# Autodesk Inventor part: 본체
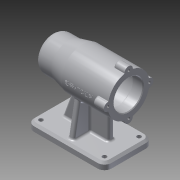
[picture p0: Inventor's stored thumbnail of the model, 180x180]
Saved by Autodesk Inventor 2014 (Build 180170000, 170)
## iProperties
Created: 2019-07
Part Number: 본체
Material: Aluminum 6061
Document SubType Name: Modeling
Designer: kh
Density: 2.71 g/cm^3
Appearance: Aluminum - Flat
Mass: 649.774 g
Surface Area: 647.594 cm^2
Volume: 239.769 cm^3
Author: kh
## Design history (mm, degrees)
sketch "Sketch1"
  geometry: L1 (-56, -35)-(56, -35); L2 (56, -35)-(56, 35); L3 (56, 35)-(-56, 35); L4 (-56, 35)-(-56, -35); L5 (-56, -35)-(56, 35); L6 (56, -35)-(-56, 35); 1 further point
  constraints: 12 end point, 2 midpoint, 2 parallel, 1 horizontal, 1 perpendicular
  dimensions: "d0" = 112 distance of L2.end L3.end; "d1" = 70 distance of L1.end L2.end
extrude "Extrusion1" new body sketch "Sketch1" distance "d2" = 10; taper "d3" = 0 deg
workplane "Work Plane1"
sketch "Sketch2"
  geometry: L1 (0, 80)-(112, 80); L2 (112, 0)-(0, 0) reference; L3 (112, 80)-(112, 110); L4 (112, 110)-(45, 110); L5 (45, 110)-(25, 105); L6 (25, 105)-(0, 105); L7 (0, 105)-(0, 80); 1 further point
  constraints: 12 end point, 2 parallel, 2 perpendicular, 1 horizontal, 1 vertical alignment
  dimensions: "d4" = 80 distance between parallel lines of L1 L2; "d5" = 60 diameter of L4 L1; "d6" = 50 diameter of L6 L1; "d7" = 25 distance of L5.end L6.end; "d8" = 45 horizontal distance of L4.end L6.end; "d9" = 112 distance between parallel lines of L3 L7
revolve "Revolution1" sketch "Sketch2" stored, may be unused: angle "d10" = 90 deg
sketch "Sketch3"
  geometry: L1 (112, 10)-(0, 10) reference; L2 (20, 10)-(39.872, 64.598); L3 (39.872, 64.598)-(87, 64.598); L4 (87, 64.598)-(87, 10); 1 further point
  constraints: 6 end point, 2 point on line, 1 parallel, 1 perpendicular
  dimensions: "d11" = 25 distance of L4.end L1.start; "d12" = 20 distance of L2.start L1.end; "d13" = 110 deg angle of L2 L1; "d14" = 47.12798 distance of L2.end L3.end
extrude "Extrusion2" join sketch "Sketch3" stored distance "d15" = 8; taper "d16" = 0 deg
workplane "Work Plane2"
sketch "Sketch4"
  geometry: L1 (-10, 70)-(-10, 0) reference; L2 (-10, 7)-(-57.334, 15.346); L3 (-10, 63)-(-57.334, 54.654); A1 r 30 centre (-80, 35) between (-50.268, 39) and (-50.268, 31) reference; 1 further point
  constraints: 4 end point, 2 point on circle, 2 point on line
  dimensions: "d18" = 7 distance of L2.start L1.end; "d19" = 7 distance of L3.start L1.start; "d20" = 100 deg angle of L3 L1; "d21" = 100 deg angle of L2 L1
extrude "Extrusion3" join sketch "Sketch4" stored distance "d22" = 8; taper "d23" = 0 deg
sketch "Sketch6"
  geometry: C1 r 6 at (0, 30); C2 r 6 at (-30, 0); C3 r 6 at (0, -30); C4 r 6 at (30, 0); 2 further points
  constraints: 4 centre point, 2 vertical alignment, 10 other
  dimensions: "d41" = 6 radius of C1; "d44" = 360 deg dimension on point (0, 0) C1.centre (derived)
extrude "Extrusion4" join sketch "Sketch6" distance "d46" = 16; taper "d47" = 0 deg
sketch "Sketch5"
  geometry: L1 (56, 80)-(-56, 80); L2 (56, 0)-(-56, 0) reference; L3 (56, 105)-(56, 55) reference; L4 (-56, 110)-(-56, 50) reference; L5 (-56, 101)-(-41, 101); L6 (-41, 101)-(-41, 101); L7 (-38, 104)-(10, 104); L8 (13, 101)-(13, 101); L9 (13, 101)-(24.7, 101); L10 (25, 100.7)-(25, 97.5); L11 (25, 97.5)-(42.7, 97.5); L12 (43, 97.2)-(43, 96); L13 (43, 96)-(46.7, 96); L14 (47, 95.7)-(47, 90.5); L15 (47, 90.5)-(47, 90.5); L16 (50, 87.5)-(50, 80); A1 r 0.3 centre (24.7, 100.7) between (25, 100.7) and (24.7, 101); A2 r 0.3 centre (42.7, 97.2) between (43, 97.2) and (42.7, 97.5); A3 r 0.3 centre (46.7, 95.7) between (47, 95.7) and (46.7, 96); A4 r 3 centre (10, 101) between (13, 101) and (10, 104); A5 r 3 centre (-38, 101) between (-38, 104) and (-41, 101); A6 r 3 centre (47, 87.5) between (50, 87.5) and (47, 90.5); 7 further points
  constraints: 26 end point, 14 point on line, 12 point on circle, 12 tangent, 8 parallel, 6 centre point, 3 equal radius, 3 perpendicular, 2 midpoint, 1 collinear, 1 horizontal
  dimensions: "d24" = 80 distance between parallel lines of L1 L2; "d25" = 42 diameter of L5 L1; "d26" = 48 diameter of L7 L1; "d27" = 42 diameter of L9 L1; "d28" = 35 diameter of L11 L1; "d29" = 32 diameter of L13 L1; "d30" = 21 diameter of L15 L1; "d31" = 15 distance of L5.start L5.end; "d32" = 54 distance of point (-41, 104) point (13, 104); "d33" = 12 distance of L8.end point (25, 101); "d34" = 18 distance of L10.end point (43, 97.5); "d35" = 3 distance of L14.end point (50, 90.5); "d36" = 4 distance of L12.end point (47, 96); "d37" = 0.3 radius of A1; "d38" = 3 radius of A4; "d39" = 3 radius of A6
revolve "Revolution2" sketch "Sketch5" stored, may be unused: angle "d40" = 90 deg
chamfer "Chamfer1" distance "d48" = 1; stored, may be unused: second distance "d49" = 2, angle "d50" = 45 deg
sketch "Sketch9"
  geometry: C1 r 22 at (30, 0) reference; C2 r 30 at (30, 0); A1 r 30 centre (30, 0) between (59.4, 5.97) and (35.97, 29.4) reference; A2 r 6 centre (30, 30) between (35.97, 29.4) and (24.03, 29.4) reference; A3 r 30 centre (30, 0) between (24.03, 29.4) and (0.6, 5.97) reference; A4 r 6 centre (0, 0) between (0.6, 5.97) and (0.6, -5.97) reference; A5 r 30 centre (30, 0) between (0.6, -5.97) and (24.03, -29.4) reference; A6 r 6 centre (30, -30) between (24.03, -29.4) and (35.97, -29.4) reference; A7 r 30 centre (30, 0) between (35.97, -29.4) and (59.4, -5.97) reference; A8 r 6 centre (60, 0) between (59.4, -5.97) and (59.4, 5.97) reference; 5 further points
  constraints: 5 coincident, 1 centre point
  dimensions: "d83" = 60 diameter of C2
hole "Hole2" sketch "Sketch9" at (30, 30), (60, 0), (30, -30), (0, 0) diameter "d84" = 3.242; stored, may be unused: countersink angle "d88" = 90 deg, drill point angle "d90" = 118 deg; dims "d85" = 8, "d86" = 4, "d87" = 2, "d89" = 11
fillet "Fillet1" dims "d66" = 3, "d67" = 10
fillet "Fillet2" dims "d68" = 1, "d72" = 3
chamfer "Chamfer3" distance "d69" = 3; stored, may be unused: second distance "d70" = 2, angle "d71" = 45 deg
fillet "Fillet3" dims "d73" = 3
workplane "Work Plane3"
sketch "Sketch7"
  geometry: L1 (-78.5, -15)-(-78.5, 15) reference; L2 (33.5, 6.771)-(33.5, 29.226) reference; 3 further points
  constraints: 1 horizontal alignment, 1 midpoint, 1 other
  dimensions: "d74" = 42 distance from line of point (-8.5, 0) L2
emboss "Emboss1" sketch "Sketch7" dims "d75" = 0.5, "d76" = 0
sketch "Sketch8"
  geometry: C1 r 3 at (-46, 25); C2 r 3 at (-46, -25); C3 r 3 at (46, -25); C4 r 3 at (46, 25); A1 r 10 centre (-46, 25) between (-46, 35) and (-56, 25) reference; A2 r 10 centre (46, 25) between (56, 25) and (46, 35) reference; A3 r 10 centre (46, -25) between (46, -35) and (56, -25) reference; A4 r 10 centre (-46, -25) between (-56, -25) and (-46, -35) reference; 1 further point
  constraints: 4 centre point, 4 coincident
  dimensions: "d77" = 6 diameter of C1; "d78" = 6 diameter of C2; "d79" = 6 diameter of C3; "d80" = 6 diameter of C4
extrude "Extrusion5" cut sketch "Sketch8" stored distance "d81" = 10; taper "d82" = 0 deg
body "Solid1"
node "Projected Loop1"
node "Projected Loop2"
other parameters: "d17" = -56
